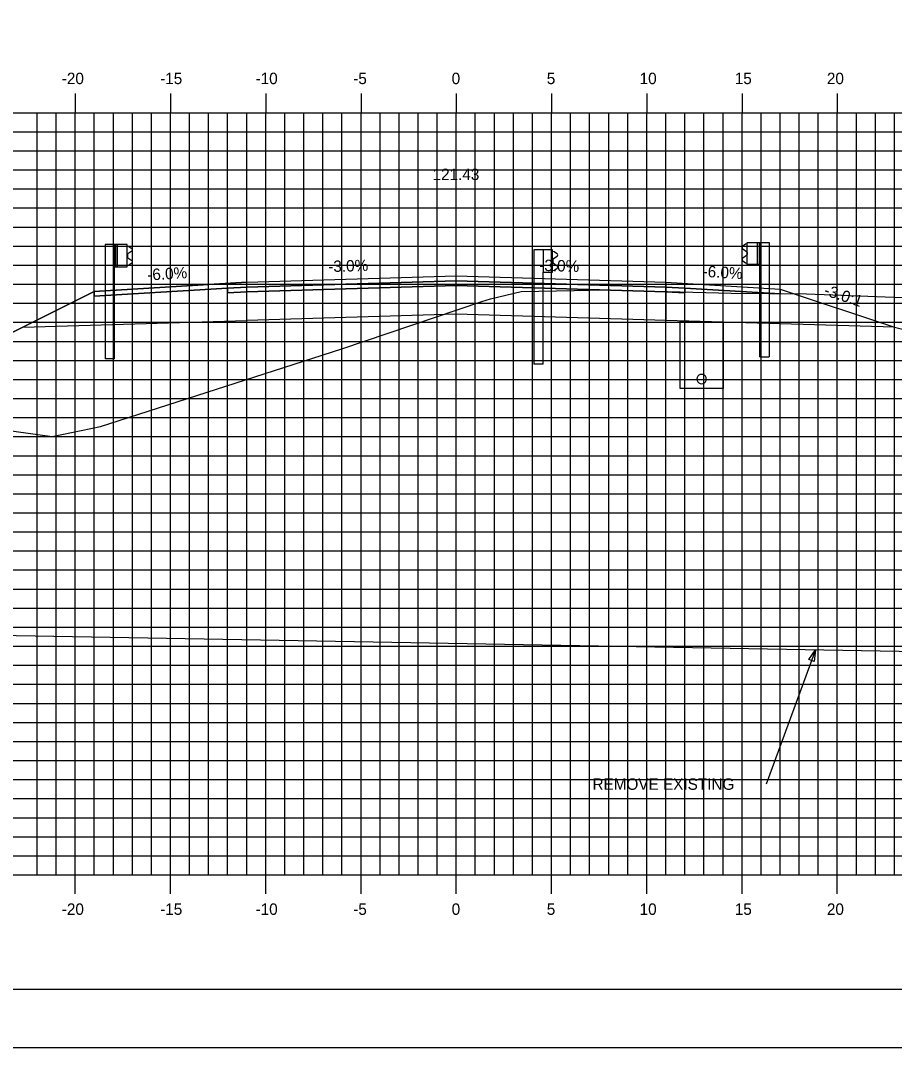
# Model space of a CAD drawing. Extents: x 850598 to 870284, y 366541 to 366651.
# Drawn here: x 858833 to 858878.9, y 366541.2 to 366595.1 of the extents above; entities that cross this region are included whole.
import ezdxf

# ---------------------------------------------------------------- set-up
doc = ezdxf.new("R2010")
doc.units = 0
for name, color, linetype in [('ANNOTATION', 7, 'Continuous'), ('BORDER', 7, 'Continuous'), ('D_Drainage_Underdrain', 7, 'Continuous'), ('D_Drainage_Underdrain_06in', 7, 'Continuous'), ('D_Guardrail_Beam_Lt', 7, 'Continuous'), ('D_Guardrail_Beam_Rt', 7, 'Continuous'), ('D_Roadway_Centerline', 7, 'Continuous'), ('D_Roadway_Centerline_Text', 7, 'Continuous'), ('D_Roadway_Edge_Shoulder', 7, 'Continuous'), ('D_Roadway_Edge_TW', 7, 'Continuous'), ('D_Roadway_Pavement', 7, 'Continuous'), ('D_Roadway_SlopeLines', 7, 'Continuous'), ('D_Roadway_SubGrade', 7, 'Continuous'), ('H_V ANNOTATION', 7, 'Continuous'), ('MAJOR', 7, 'Continuous'), ('MINOR', 7, 'Continuous'), ('PLOT BOUNDARY', 7, 'Continuous'), ('S_Drainage_Culvert_Top', 7, 'Continuous'), ('S_Guardrail_Beam', 7, 'Continuous'), ('S_Roadway_Centerline', 7, 'Continuous')]:
    doc.layers.add(name, color=color, linetype=linetype)

msp = doc.modelspace()

# ---------------------------------------------------------------- linework, layer by layer
at = {"layer": 'BORDER'}
msp.add_line((858810.889, 366544.225), (858970.889, 366544.225), dxfattribs=at)
at = {"layer": 'D_Drainage_Underdrain'}
msp.add_lwpolyline([(858869.889, 366579.244), (858869.889, 366575.744), (858867.639, 366575.744), (858867.639, 366579.289)], close=True, dxfattribs=at)
at = {"layer": 'D_Drainage_Underdrain_06in'}
msp.add_lwpolyline([(858868.764, 366576.494), (858868.687, 366576.482), (858868.617, 366576.446), (858868.562, 366576.391), (858868.526, 366576.321), (858868.514, 366576.244), (858868.526, 366576.167), (858868.562, 366576.097), (858868.617, 366576.042), (858868.687, 366576.006), (858868.764, 366575.994), (858868.841, 366576.006), (858868.911, 366576.042), (858868.966, 366576.097), (858869.002, 366576.167), (858869.014, 366576.244), (858869.002, 366576.321), (858868.966, 366576.391), (858868.911, 366576.446), (858868.841, 366576.482)], close=True, dxfattribs=at)
at = {"layer": 'D_Guardrail_Beam_Lt'}
for p, q in [((858837.46, 366583.3), (858837.46, 366577.3)), ((858837.931, 366583.3), (858837.46, 366583.3)), ((858838.618, 366583.3), (858837.931, 366583.3)), ((858837.931, 366583.3), (858837.931, 366582.133)), ((858837.993, 366583.3), (858837.993, 366582.133)), ((858838.097, 366583.3), (858838.097, 366582.133)), ((858838.618, 366582.133), (858838.618, 366583.3)), ((858838.618, 366583.225), (858838.692, 366583.213)), ((858838.852, 366582.963), (858838.656, 366582.826)), ((858838.708, 366583.206), (858838.852, 366583.106)), ((858838.623, 366582.762), (858838.623, 366582.671)), ((858838.656, 366582.607), (858838.852, 366582.47)), ((858837.931, 366582.133), (858838.618, 366582.133)), ((858837.952, 366577.3), (858837.952, 366582.133)), ((858838.692, 366582.221), (858838.618, 366582.208)), ((858838.852, 366582.327), (858838.708, 366582.227)), ((858837.952, 366577.3), (858837.46, 366577.3))]:
    msp.add_line(p, q, dxfattribs=at)
for centre, major_axis, start_param, end_param in [((858838.684, 366583.172), (0.0417, 0), 0.959931, 1.396263), ((858838.801, 366583.034), (0.0877, 0), 5.323254, 7.243116), ((858838.702, 366582.762), (-0.0789, 0), 5.323254, 6.283185), ((858838.702, 366582.671), (-0.0789, 0), 6.283185, 7.243116), ((858838.801, 366582.399), (0.0877, 0), 5.323254, 7.243116), ((858838.684, 366582.261), (0.0417, 0), 4.886922, 5.323254)]:
    msp.add_ellipse(centre, major_axis=major_axis, ratio=0.995501, start_param=start_param, end_param=end_param, dxfattribs=at)
at = {"layer": 'D_Guardrail_Beam_Rt'}
for p, q in [((858871.07, 366583.326), (858870.927, 366583.226)), ((858870.927, 366583.083), (858871.122, 366582.946)), ((858871.16, 366583.345), (858871.087, 366583.333)), ((858871.16, 366583.42), (858871.847, 366583.42)), ((858871.16, 366582.253), (858871.16, 366583.42)), ((858871.681, 366583.42), (858871.681, 366582.253)), ((858871.785, 366583.42), (858871.785, 366582.253)), ((858871.847, 366583.42), (858872.318, 366583.42)), ((858871.847, 366583.42), (858871.847, 366582.253)), ((858872.318, 366583.42), (858872.318, 366577.42)), ((858871.122, 366582.727), (858870.927, 366582.59)), ((858870.927, 366582.447), (858871.07, 366582.347)), ((858871.156, 366582.882), (858871.156, 366582.791)), ((858871.087, 366582.341), (858871.16, 366582.328)), ((858871.847, 366582.253), (858871.16, 366582.253)), ((858871.827, 366577.42), (858871.827, 366582.253)), ((858871.827, 366577.42), (858872.318, 366577.42))]:
    msp.add_line(p, q, dxfattribs=at)
for centre, major_axis, start_param, end_param in [((858870.977, 366583.154), (-0.0877, 0), 5.323254, 7.243116), ((858871.094, 366583.292), (-0.0417, 0), 4.886922, 5.323254), ((858871.077, 366582.882), (0.0789, 0), 0, 0.959931), ((858870.977, 366582.519), (-0.0877, 0), 5.323254, 7.243116), ((858871.077, 366582.791), (0.0789, 0), 5.323254, 6.283185), ((858871.094, 366582.381), (-0.0417, 0), 0.959931, 1.396263)]:
    msp.add_ellipse(centre, major_axis=major_axis, ratio=0.995501, start_param=start_param, end_param=end_param, dxfattribs=at)
at = {"layer": 'D_Roadway_Centerline'}
msp.add_lwpolyline([(858824.61, 366574.707), (858826.889, 366575.847), (858833.144, 366578.974), (858836.889, 366580.847), (858838.889, 366580.967), (858844.889, 366581.327), (858855.889, 366581.657), (858866.889, 366581.327), (858870.889, 366581.087), (858872.889, 366580.967), (858878.889, 366578.967), (858922.12, 366568.225), (858936.406, 366564.676), (858946.268, 366562.225), (858950.268, 366562.225)], dxfattribs=at)
at = {"layer": 'D_Roadway_Edge_Shoulder'}
for points in [[(858844.889, 366581.327), (858838.889, 366580.967), (858838.889, 366580.967), (858836.889, 366580.847), (858836.889, 366580.597), (858843.889, 366581.017), (858844.889, 366581.077)], [(858866.889, 366581.327), (858870.889, 366581.087), (858870.889, 366581.087), (858872.889, 366580.967), (858872.889, 366580.717), (858867.889, 366581.017), (858866.889, 366581.077)]]:
    msp.add_lwpolyline(points, close=True, dxfattribs=at)
at = {"layer": 'D_Roadway_Edge_TW'}
msp.add_lwpolyline([(858844.889, 366581.077), (858844.889, 366581.327), (858855.889, 366581.657), (858866.889, 366581.327), (858866.889, 366581.077), (858855.889, 366581.407)], close=True, dxfattribs=at)
at = {"layer": 'D_Roadway_Pavement'}
for points in [[(858844.889, 366580.827), (858844.889, 366581.077), (858855.889, 366581.407), (858866.889, 366581.077), (858866.889, 366580.827), (858855.889, 366581.157)], [(858844.889, 366581.077), (858843.889, 366581.017), (858843.889, 366580.767), (858844.889, 366580.827)], [(858866.889, 366581.077), (858867.889, 366581.017), (858867.889, 366580.767), (858866.889, 366580.827)]]:
    msp.add_lwpolyline(points, close=True, dxfattribs=at)
at = {"layer": 'D_Roadway_SlopeLines'}
msp.add_lwpolyline([(858836.889, 366580.847), (858826.889, 366575.847)], dxfattribs=at)
at = {"layer": 'D_Roadway_SubGrade'}
for points in [[(858844.889, 366580.827), (858843.889, 366580.767), (858843.889, 366581.017), (858836.889, 366580.597), (858836.889, 366580.847), (858833.144, 366578.974), (858844.889, 366579.327)], [(858844.889, 366579.327), (858844.889, 366580.827), (858855.889, 366581.157), (858866.889, 366580.827), (858866.889, 366579.327), (858855.889, 366579.657)], [(858866.889, 366580.827), (858867.889, 366580.767), (858867.889, 366581.017), (858872.889, 366580.717), (858872.889, 366580.967), (858878.889, 366578.967), (858866.889, 366579.327)]]:
    msp.add_lwpolyline(points, close=True, dxfattribs=at)
msp.add_lwpolyline([(858836.889, 366580.847), (858833.144, 366578.974), (858836.889, 366580.847)], dxfattribs=at)
at = {"layer": 'H_V ANNOTATION'}
msp.add_line((858874.741, 366562.03), (858872.148, 366554.988), dxfattribs=at)
msp.add_lwpolyline([(858874.393, 366561.519), (858874.741, 366562.03), (858874.675, 366561.416)], close=True, dxfattribs=at)
at = {"layer": 'MAJOR'}
for p, q in [((858835.889, 366591.227), (858835.889, 366590.225)), ((858835.889, 366591.227), (858835.889, 366590.225)), ((858840.889, 366591.227), (858840.889, 366590.225)), ((858840.889, 366591.227), (858840.889, 366590.225)), ((858845.889, 366591.227), (858845.889, 366590.225)), ((858845.889, 366591.227), (858845.889, 366590.225)), ((858850.889, 366591.227), (858850.889, 366590.225)), ((858850.889, 366591.227), (858850.889, 366590.225)), ((858855.889, 366591.227), (858855.889, 366590.225)), ((858855.889, 366591.227), (858855.889, 366590.225)), ((858860.889, 366591.227), (858860.889, 366590.225)), ((858860.889, 366591.227), (858860.889, 366590.225)), ((858865.889, 366591.227), (858865.889, 366590.225)), ((858865.889, 366591.227), (858865.889, 366590.225)), ((858870.889, 366591.227), (858870.889, 366590.225)), ((858870.889, 366591.227), (858870.889, 366590.225)), ((858875.889, 366591.227), (858875.889, 366590.225)), ((858875.889, 366591.227), (858875.889, 366590.225)), ((858815.889, 366590.225), (858955.889, 366590.225)), ((858815.889, 366590.225), (858955.889, 366590.225)), ((858815.889, 366590.225), (858955.889, 366590.225)), ((858815.889, 366590.225), (858955.889, 366590.225)), ((858835.889, 366550.225), (858835.889, 366590.225)), ((858835.889, 366550.225), (858835.889, 366590.225)), ((858840.889, 366550.225), (858840.889, 366590.225)), ((858840.889, 366550.225), (858840.889, 366590.225)), ((858845.889, 366550.225), (858845.889, 366590.225)), ((858845.889, 366550.225), (858845.889, 366590.225)), ((858850.889, 366550.225), (858850.889, 366590.225)), ((858850.889, 366550.225), (858850.889, 366590.225)), ((858855.889, 366550.225), (858855.889, 366590.225)), ((858855.889, 366550.225), (858855.889, 366590.225)), ((858860.889, 366550.225), (858860.889, 366590.225)), ((858860.889, 366550.225), (858860.889, 366590.225)), ((858865.889, 366550.225), (858865.889, 366590.225)), ((858865.889, 366550.225), (858865.889, 366590.225)), ((858870.889, 366550.225), (858870.889, 366590.225)), ((858870.889, 366550.225), (858870.889, 366590.225)), ((858875.889, 366550.225), (858875.889, 366590.225)), ((858875.889, 366550.225), (858875.889, 366590.225)), ((858815.889, 366585.225), (858955.889, 366585.225)), ((858815.889, 366585.225), (858955.889, 366585.225)), ((858815.889, 366580.225), (858955.889, 366580.225)), ((858815.889, 366580.225), (858955.889, 366580.225)), ((858815.889, 366575.225), (858955.889, 366575.225)), ((858815.889, 366575.225), (858955.889, 366575.225)), ((858815.889, 366570.225), (858955.889, 366570.225)), ((858815.889, 366570.225), (858955.889, 366570.225)), ((858815.889, 366565.225), (858955.889, 366565.225)), ((858815.889, 366565.225), (858955.889, 366565.225)), ((858815.889, 366560.225), (858955.889, 366560.225)), ((858815.889, 366560.225), (858955.889, 366560.225)), ((858815.889, 366555.225), (858955.889, 366555.225)), ((858815.889, 366555.225), (858955.889, 366555.225)), ((858815.889, 366550.225), (858955.889, 366550.225)), ((858815.889, 366550.225), (858955.889, 366550.225)), ((858815.889, 366550.225), (858955.889, 366550.225)), ((858815.889, 366550.225), (858955.889, 366550.225)), ((858835.889, 366549.223), (858835.889, 366550.225)), ((858835.889, 366549.223), (858835.889, 366550.225)), ((858840.889, 366549.223), (858840.889, 366550.225)), ((858840.889, 366549.223), (858840.889, 366550.225)), ((858845.889, 366549.223), (858845.889, 366550.225)), ((858845.889, 366549.223), (858845.889, 366550.225)), ((858850.889, 366549.223), (858850.889, 366550.225)), ((858850.889, 366549.223), (858850.889, 366550.225)), ((858855.889, 366549.223), (858855.889, 366550.225)), ((858855.889, 366549.223), (858855.889, 366550.225)), ((858860.889, 366549.223), (858860.889, 366550.225)), ((858860.889, 366549.223), (858860.889, 366550.225)), ((858865.889, 366549.223), (858865.889, 366550.225)), ((858865.889, 366549.223), (858865.889, 366550.225)), ((858870.889, 366549.223), (858870.889, 366550.225)), ((858870.889, 366549.223), (858870.889, 366550.225)), ((858875.889, 366549.223), (858875.889, 366550.225)), ((858875.889, 366549.223), (858875.889, 366550.225))]:
    msp.add_line(p, q, dxfattribs=at)
at = {"layer": 'MINOR'}
for p, q in [((858833.889, 366550.225), (858833.889, 366590.225)), ((858833.889, 366550.225), (858833.889, 366590.225)), ((858834.889, 366550.225), (858834.889, 366590.225)), ((858834.889, 366550.225), (858834.889, 366590.225)), ((858836.889, 366550.225), (858836.889, 366590.225)), ((858836.889, 366550.225), (858836.889, 366590.225)), ((858837.889, 366550.225), (858837.889, 366590.225)), ((858837.889, 366550.225), (858837.889, 366590.225)), ((858838.889, 366550.225), (858838.889, 366590.225)), ((858838.889, 366550.225), (858838.889, 366590.225)), ((858839.889, 366550.225), (858839.889, 366590.225)), ((858839.889, 366550.225), (858839.889, 366590.225)), ((858841.889, 366550.225), (858841.889, 366590.225)), ((858841.889, 366550.225), (858841.889, 366590.225)), ((858842.889, 366550.225), (858842.889, 366590.225)), ((858842.889, 366550.225), (858842.889, 366590.225)), ((858843.889, 366550.225), (858843.889, 366590.225)), ((858843.889, 366550.225), (858843.889, 366590.225)), ((858844.889, 366550.225), (858844.889, 366590.225)), ((858844.889, 366550.225), (858844.889, 366590.225)), ((858846.889, 366550.225), (858846.889, 366590.225)), ((858846.889, 366550.225), (858846.889, 366590.225)), ((858847.889, 366550.225), (858847.889, 366590.225)), ((858847.889, 366550.225), (858847.889, 366590.225)), ((858848.889, 366550.225), (858848.889, 366590.225)), ((858848.889, 366550.225), (858848.889, 366590.225)), ((858849.889, 366550.225), (858849.889, 366590.225)), ((858849.889, 366550.225), (858849.889, 366590.225)), ((858851.889, 366550.225), (858851.889, 366590.225)), ((858851.889, 366550.225), (858851.889, 366590.225)), ((858852.889, 366550.225), (858852.889, 366590.225)), ((858852.889, 366550.225), (858852.889, 366590.225)), ((858853.889, 366550.225), (858853.889, 366590.225)), ((858853.889, 366550.225), (858853.889, 366590.225)), ((858854.889, 366550.225), (858854.889, 366590.225)), ((858854.889, 366550.225), (858854.889, 366590.225)), ((858856.889, 366550.225), (858856.889, 366590.225)), ((858856.889, 366550.225), (858856.889, 366590.225)), ((858857.889, 366550.225), (858857.889, 366590.225)), ((858857.889, 366550.225), (858857.889, 366590.225)), ((858858.889, 366550.225), (858858.889, 366590.225)), ((858858.889, 366550.225), (858858.889, 366590.225)), ((858859.889, 366550.225), (858859.889, 366590.225)), ((858859.889, 366550.225), (858859.889, 366590.225)), ((858861.889, 366550.225), (858861.889, 366590.225)), ((858861.889, 366550.225), (858861.889, 366590.225)), ((858862.889, 366550.225), (858862.889, 366590.225)), ((858862.889, 366550.225), (858862.889, 366590.225)), ((858863.889, 366550.225), (858863.889, 366590.225)), ((858863.889, 366550.225), (858863.889, 366590.225)), ((858864.889, 366550.225), (858864.889, 366590.225)), ((858864.889, 366550.225), (858864.889, 366590.225)), ((858866.889, 366550.225), (858866.889, 366590.225)), ((858866.889, 366550.225), (858866.889, 366590.225)), ((858867.889, 366550.225), (858867.889, 366590.225)), ((858867.889, 366550.225), (858867.889, 366590.225)), ((858868.889, 366550.225), (858868.889, 366590.225)), ((858868.889, 366550.225), (858868.889, 366590.225)), ((858869.889, 366550.225), (858869.889, 366590.225)), ((858869.889, 366550.225), (858869.889, 366590.225)), ((858871.889, 366550.225), (858871.889, 366590.225)), ((858871.889, 366550.225), (858871.889, 366590.225)), ((858872.889, 366550.225), (858872.889, 366590.225)), ((858872.889, 366550.225), (858872.889, 366590.225)), ((858873.889, 366550.225), (858873.889, 366590.225)), ((858873.889, 366550.225), (858873.889, 366590.225)), ((858874.889, 366550.225), (858874.889, 366590.225)), ((858874.889, 366550.225), (858874.889, 366590.225)), ((858876.889, 366550.225), (858876.889, 366590.225)), ((858876.889, 366550.225), (858876.889, 366590.225)), ((858877.889, 366550.225), (858877.889, 366590.225)), ((858877.889, 366550.225), (858877.889, 366590.225)), ((858878.889, 366550.225), (858878.889, 366590.225)), ((858878.889, 366550.225), (858878.889, 366590.225)), ((858815.889, 366589.225), (858955.889, 366589.225)), ((858815.889, 366589.225), (858955.889, 366589.225)), ((858815.889, 366588.225), (858955.889, 366588.225)), ((858815.889, 366588.225), (858955.889, 366588.225)), ((858815.889, 366587.225), (858955.889, 366587.225)), ((858815.889, 366587.225), (858955.889, 366587.225)), ((858815.889, 366586.225), (858955.889, 366586.225)), ((858815.889, 366586.225), (858955.889, 366586.225)), ((858815.889, 366584.225), (858955.889, 366584.225)), ((858815.889, 366584.225), (858955.889, 366584.225)), ((858815.889, 366583.225), (858955.889, 366583.225)), ((858815.889, 366583.225), (858955.889, 366583.225)), ((858815.889, 366582.225), (858955.889, 366582.225)), ((858815.889, 366582.225), (858955.889, 366582.225)), ((858815.889, 366581.225), (858955.889, 366581.225)), ((858815.889, 366581.225), (858955.889, 366581.225)), ((858815.889, 366579.225), (858955.889, 366579.225)), ((858815.889, 366579.225), (858955.889, 366579.225)), ((858815.889, 366578.225), (858955.889, 366578.225)), ((858815.889, 366578.225), (858955.889, 366578.225)), ((858815.889, 366577.225), (858955.889, 366577.225)), ((858815.889, 366577.225), (858955.889, 366577.225)), ((858815.889, 366576.225), (858955.889, 366576.225)), ((858815.889, 366576.225), (858955.889, 366576.225)), ((858815.889, 366574.225), (858955.889, 366574.225)), ((858815.889, 366574.225), (858955.889, 366574.225)), ((858815.889, 366573.225), (858955.889, 366573.225)), ((858815.889, 366573.225), (858955.889, 366573.225)), ((858815.889, 366572.225), (858955.889, 366572.225)), ((858815.889, 366572.225), (858955.889, 366572.225)), ((858815.889, 366571.225), (858955.889, 366571.225)), ((858815.889, 366571.225), (858955.889, 366571.225)), ((858815.889, 366569.225), (858955.889, 366569.225)), ((858815.889, 366569.225), (858955.889, 366569.225)), ((858815.889, 366568.225), (858955.889, 366568.225)), ((858815.889, 366568.225), (858955.889, 366568.225)), ((858815.889, 366567.225), (858955.889, 366567.225)), ((858815.889, 366567.225), (858955.889, 366567.225)), ((858815.889, 366566.225), (858955.889, 366566.225)), ((858815.889, 366566.225), (858955.889, 366566.225)), ((858815.889, 366564.225), (858955.889, 366564.225)), ((858815.889, 366564.225), (858955.889, 366564.225)), ((858815.889, 366563.225), (858955.889, 366563.225)), ((858815.889, 366563.225), (858955.889, 366563.225)), ((858815.889, 366562.225), (858955.889, 366562.225)), ((858815.889, 366562.225), (858955.889, 366562.225)), ((858815.889, 366561.225), (858955.889, 366561.225)), ((858815.889, 366561.225), (858955.889, 366561.225)), ((858815.889, 366559.225), (858955.889, 366559.225)), ((858815.889, 366559.225), (858955.889, 366559.225)), ((858815.889, 366558.225), (858955.889, 366558.225)), ((858815.889, 366558.225), (858955.889, 366558.225)), ((858815.889, 366557.225), (858955.889, 366557.225)), ((858815.889, 366557.225), (858955.889, 366557.225)), ((858815.889, 366556.225), (858955.889, 366556.225)), ((858815.889, 366556.225), (858955.889, 366556.225)), ((858815.889, 366554.225), (858955.889, 366554.225)), ((858815.889, 366554.225), (858955.889, 366554.225)), ((858815.889, 366553.225), (858955.889, 366553.225)), ((858815.889, 366553.225), (858955.889, 366553.225)), ((858815.889, 366552.225), (858955.889, 366552.225)), ((858815.889, 366552.225), (858955.889, 366552.225)), ((858815.889, 366551.225), (858955.889, 366551.225)), ((858815.889, 366551.225), (858955.889, 366551.225))]:
    msp.add_line(p, q, dxfattribs=at)
at = {"layer": 'PLOT BOUNDARY'}
msp.add_lwpolyline([(858802.796, 366541.166), (858972.796, 366541.166), (858972.796, 366651.166), (858802.796, 366651.166)], close=True, dxfattribs=at)
at = {"layer": 'S_Drainage_Culvert_Top'}
msp.add_line((858923.634, 366561.16), (858825.849, 366562.901), dxfattribs=at)
at = {"layer": 'S_Guardrail_Beam'}
for p, q in [((858859.956, 366583.023), (858859.956, 366577.023)), ((858860.448, 366583.023), (858859.956, 366583.023)), ((858860.937, 366583.023), (858860.448, 366583.023)), ((858860.448, 366583.023), (858860.448, 366581.856)), ((858860.937, 366581.856), (858860.937, 366583.023)), ((858860.937, 366582.95), (858861.019, 366582.936)), ((858861.036, 366582.929), (858861.18, 366582.829)), ((858860.95, 366582.485), (858860.95, 366582.394)), ((858861.18, 366582.686), (858860.984, 366582.549)), ((858860.448, 366577.023), (858860.448, 366581.856)), ((858860.448, 366581.856), (858860.937, 366581.856)), ((858861.019, 366581.944), (858860.937, 366581.929)), ((858860.984, 366582.33), (858861.18, 366582.194)), ((858861.18, 366582.05), (858861.036, 366581.95)), ((858860.448, 366577.023), (858859.956, 366577.023))]:
    msp.add_line(p, q, dxfattribs=at)
for centre, major_axis, start_param, end_param in [((858861.012, 366582.895), (0.0417, 0), 0.959931, 1.396263), ((858861.029, 366582.485), (-0.0789, 0), 5.323254, 6.283185), ((858861.029, 366582.394), (-0.0789, 0), 6.283185, 7.243116), ((858861.129, 366582.757), (0.0877, 0), 5.323254, 7.243116), ((858861.012, 366581.984), (0.0417, 0), 4.886922, 5.323254), ((858861.129, 366582.122), (0.0877, 0), 5.323254, 7.243116)]:
    msp.add_ellipse(centre, major_axis=major_axis, ratio=0.995501, start_param=start_param, end_param=end_param, dxfattribs=at)
at = {"layer": 'S_Roadway_Centerline'}
msp.add_lwpolyline([(858815.889, 366576.387), (858819.033, 366576.498), (858821.039, 366575.547), (858825.465, 366574.506), (858834.683, 366573.236), (858837.215, 366573.751), (858849.885, 366577.839), (858857.238, 366580.308), (858857.682, 366580.449), (858859.303, 366580.84), (858862.082, 366580.89), (858863.626, 366580.923), (858870.309, 366580.761), (858874.271, 366580.712), (858881.174, 366580.458)], dxfattribs=at)

# ---------------------------------------------------------------- texts
at = {"layer": 'ANNOTATION'}
for s, rotation, p in [('-3.0%', 1.7184, (858849.177, 366581.856)), ('-3.0%', 358.2816, (858860.237, 366581.927)), ('-6.0%', 3.4336, (858839.686, 366581.416)), ('-6.0%', 356.5664, (858868.806, 366581.613)), ('-3.0:1', 341.5651, (858875.143, 366580.669))]:
    msp.add_text(s, height=0.6, rotation=rotation, dxfattribs=at).set_placement(p)
at = {"layer": 'D_Roadway_Centerline'}
for s, p in [('C', (858855.884, 366581.657)), ('C', (858855.884, 366581.657)), ('L', (858855.889, 366581.649)), ('L', (858855.889, 366581.649))]:
    msp.add_text(s, height=0.0146, dxfattribs=at).set_placement(p)
at = {"layer": 'D_Roadway_Centerline_Text'}
msp.add_text('121.43', height=0.6, dxfattribs=at).set_placement((858854.645, 366586.689))
at = {"layer": 'H_V ANNOTATION'}
for s, p in [('-20', (858835.183, 366591.725)), ('-15', (858840.346, 366591.725)), ('-10', (858845.354, 366591.725)), ('-5', (858850.48, 366591.725)), ('0', (858855.648, 366591.725)), ('5', (858860.64, 366591.725)), ('10', (858865.514, 366591.725)), ('15', (858870.506, 366591.725)), ('20', (858875.343, 366591.725)), ('REMOVE EXISTING', (858863.039, 366554.688)), ('-20', (858835.183, 366548.125)), ('-15', (858840.346, 366548.125)), ('-10', (858845.354, 366548.125)), ('-5', (858850.48, 366548.125)), ('0', (858855.648, 366548.125)), ('5', (858860.64, 366548.125)), ('10', (858865.514, 366548.125)), ('15', (858870.506, 366548.125)), ('20', (858875.343, 366548.125))]:
    msp.add_text(s, height=0.6, dxfattribs=at).set_placement(p)
at = {"layer": 'S_Roadway_Centerline'}
for s, p in [('C', (858874.266, 366580.712)), ('L', (858874.271, 366580.705))]:
    msp.add_text(s, height=0.0146, dxfattribs=at).set_placement(p)

doc.saveas('drawing.dxf')
